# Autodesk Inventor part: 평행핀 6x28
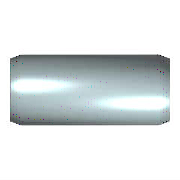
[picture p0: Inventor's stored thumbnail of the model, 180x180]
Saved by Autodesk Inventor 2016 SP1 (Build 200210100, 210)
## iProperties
Created: 2012-02
Part Number: 평행핀 6x28
Material: 스테인리스강
Description: 평행 핀
Document SubType Name: Modeling
Standard: KS B 1320
Designer: mduedu
Standards Organization: KS
Language: ko-KR
Size Designation: B 6 x  28
Categories: <MemberInstance><Categories><Category DisplayName="조임쇠" InternalName="e4da775c-781d-43d5-af7c-5136215cf5a6" Mnemonic="FSTN"><Category DisplayName="핀" InternalNa
Density: 1 g/cm^3
Appearance: 주황색
IsCustomPart: 1
Author: mduedu
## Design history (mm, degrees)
sketch "스케치"
  geometry: C1 r 3 at (0, 0); 1 further point
  constraints: 1 centre point, 1 coincident
  dimensions: "d1" = 6 diameter of C1 (= NND)
extrude "본체" new body sketch "스케치" distance "d2" = 28 (= NLG); taper "d3" = 0 deg
chamfer "스케치2" distance "d8" = 1.2 (= PHH); stored, may be unused: angle "d9" = 15 deg (= FAWI), second distance "d12" = 1.2 (= PHH)
node "작업 평면1"
node "작업 평면2"
body "Solid1"
chamfer "모따기1" distance "d4" = 1.2 (= PHH); stored, may be unused: angle "d5" = 15 deg (= FAWI), second distance "d11" = 1.2 (= PHH)
other parameters: "NND" = 6 [user parameter; used in 1 equation term], "NLG" = 28 [user parameter; used in 1 equation term], "PHH" = 1.2 [user parameter; used in 4 equation terms], "FAWI" = 15 deg [user parameter; used in 2 equation terms], "d13" = 0, "d15" = 0, "d16" = 0, "KAH" = 0.8 [user parameter]
